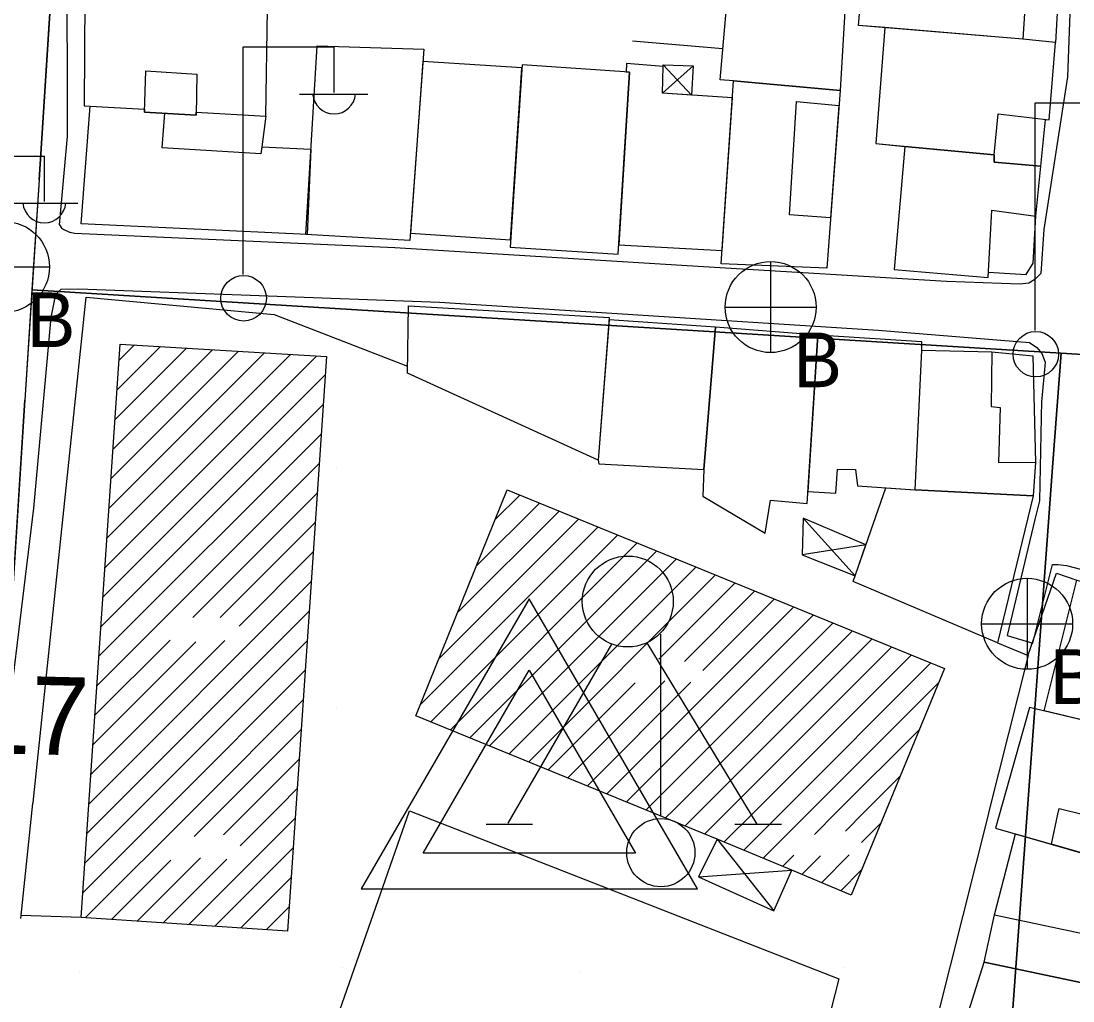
# Model space of a CAD drawing. Extents: x 417997 to 421451, y 4451742 to 4455216.
# Drawn here: x 419832.6 to 419913.6, y 4453026.6 to 4453102 of the extents above; entities that cross this region are included whole.
import ezdxf

# ---------------------------------------------------------------- set-up
doc = ezdxf.new("R2010")
doc.units = 0
for name, color, linetype in [('ADA', 7, 'Continuous'), ('ADAKENARI', 7, 'Continuous'), ('B_Mesken', 7, 'Continuous'), ('B_Okul', 7, 'Continuous'), ('B_Spor_Tesisleri', 7, 'Continuous'), ('B_Sundurma', 7, 'Continuous'), ('B_Tarama', 7, 'Continuous'), ('B_Teras', 7, 'Continuous'), ('Default', 7, 'Continuous'), ('LJ_SEMBOL', 7, 'Continuous'), ('PL_AYA_PARK_DINLENME', 7, 'Continuous'), ('PL_EĞİTİM', 7, 'Continuous'), ('PL_TİCK', 7, 'Continuous'), ('S_Bayrak_Diregi', 7, 'Continuous'), ('S_Elektrik_Diregi', 7, 'Continuous'), ('S_Heykel', 7, 'Continuous'), ('S_Rogar_Kapagi_Buski', 7, 'Continuous'), ('Sinir_Duvar_tek_tarafa_ait', 7, 'Continuous'), ('TR_EĞİTİM', 7, 'Continuous'), ('TR_TİCK', 7, 'Continuous'), ('Y_Yol_Kotu', 7, 'Continuous'), ('Yol_Sose', 7, 'Continuous')]:
    doc.layers.add(name, color=color, linetype=linetype)

# ---------------------------------------------------------------- blocks, each defined once
blk = doc.blocks.new('POINT_DISPLAY')
at = {"layer": 'Default'}
blk.add_line((0, 0), (0, 0), dxfattribs=at)

msp = doc.modelspace()

# ---------------------------------------------------------------- linework, layer by layer
at = {"layer": 'ADA'}
for p, q in [((419951.154, 4453074.072), (419833.483, 4453081.316)), ((419951.154, 4453074.072), (419833.483, 4453081.316)), ((419912.691, 4453076.44), (419912.059, 4453068.004)), ((419912.691, 4453076.44), (419912.059, 4453068.004)), ((419905.437, 4452977.718), (419912.059, 4453068.004)), ((419905.437, 4452977.718), (419912.059, 4453068.004))]:
    msp.add_line(p, q, dxfattribs=at)
at = {"layer": 'ADAKENARI'}
for p, q in [((419834.027, 4453089.798), (419841.779, 4453210.729)), ((419834.027, 4453089.798), (419841.779, 4453210.729)), ((419834.027, 4453089.798), (419832.939, 4453072.833)), ((419834.027, 4453089.798), (419832.939, 4453072.833)), ((419830.093, 4453028.46), (419832.939, 4453072.833)), ((419830.093, 4453028.46), (419832.939, 4453072.833))]:
    msp.add_line(p, q, dxfattribs=at)
at = {"layer": 'B_Mesken'}
for points in [[(419912.76, 4453109.492), (419912.249, 4453100.365), (419909.73, 4453100.607), (419899.124, 4453101.5), (419897.089, 4453101.672), (419897.842, 4453110.551), (419898.362, 4453110.516), (419908.156, 4453109.853), (419910.33, 4453109.706)], [(419887.48, 4453097.401), (419886.457, 4453097.488), (419887.377, 4453108.059), (419896.334, 4453107.579), (419895.672, 4453096.673), (419895.672, 4453096.673), (419895.672, 4453096.673)], [(419846.114, 4453095.004), (419851.487, 4453094.675), (419851.61, 4453102.935), (419837.555, 4453103.855), (419837.512, 4453095.489), (419842.152, 4453095.224), (419842.144, 4453095.006), (419846.109, 4453094.775)], [(419911.125, 4453090.846), (419911.48, 4453094.436), (419911.76, 4453094.404), (419912.249, 4453100.365), (419909.73, 4453100.607), (419899.124, 4453101.5), (419898.436, 4453092.571), (419898.436, 4453092.571), (419900.66, 4453092.36), (419907.525, 4453091.709), (419907.534, 4453091.153)], [(419855.422, 4453100.093), (419863.647, 4453099.837), (419862.575, 4453085.128), (419854.553, 4453085.575)], [(419871.185, 4453098.399), (419863.577, 4453098.886), (419862.615, 4453085.67), (419870.316, 4453085.18)], [(419871.2, 4453098.623), (419870.278, 4453084.602), (419878.603, 4453084.075), (419879.459, 4453098.082)], [(419878.646, 4453084.778), (419886.59, 4453084.354), (419887.39, 4453096.087), (419882.002, 4453096.446), (419882.066, 4453098.508), (419879.252, 4453098.748), (419879.221, 4453098.097), (419879.459, 4453098.082)], [(419886.52, 4453083.315), (419887.48, 4453097.401), (419895.672, 4453096.673), (419894.658, 4453082.983)], [(419851.167, 4453092.337), (419854.947, 4453092.149), (419854.67, 4453085.568), (419837.26, 4453086.406), (419837.956, 4453095.463), (419842.152, 4453095.224), (419842.144, 4453095.006), (419843.745, 4453094.913), (419846.109, 4453094.775), (419846.114, 4453095.004), (419851.487, 4453094.675)], [(419907.088, 4453082.688), (419909.991, 4453082.499), (419910.533, 4453083.385), (419910.741, 4453086.987), (419911.125, 4453090.846), (419907.534, 4453091.153), (419907.525, 4453091.709), (419900.66, 4453092.36), (419899.844, 4453082.875), (419907.063, 4453082.27)], [(419862.386, 4453074.902), (419862.461, 4453080.093), (419877.915, 4453079.194), (419877.052, 4453068.221)], [(419877.052, 4453068.221), (419877.113, 4453067.929), (419885.192, 4453067.495), (419886.101, 4453078.439), (419877.9, 4453079.008)], [(419885.192, 4453067.495), (419885.117, 4453065.441), (419889.914, 4453062.6), (419890.313, 4453065.126), (419893.136, 4453064.869), (419893.964, 4453077.833), (419886.101, 4453078.439)], [(419901.964, 4453076.668), (419901.964, 4453077.308), (419893.964, 4453077.833), (419893.195, 4453065.796), (419895.35, 4453065.681), (419895.482, 4453067.51), (419896.872, 4453067.5), (419897.006, 4453066.233), (419901.454, 4453065.923), (419901.964, 4453076.668)], [(419907.35, 4453076.547), (419910.502, 4453076.242), (419910.71, 4453068.072), (419910.537, 4453065.469), (419901.454, 4453065.923), (419901.964, 4453076.668)], [(419896.677, 4453058.877), (419899.188, 4453066.081), (419901.454, 4453065.923), (419910.537, 4453065.469), (419907.8, 4453054.166)], [(419911.39, 4453048.913), (419913.893, 4453058.99), (419925.145, 4453056.243), (419922.654, 4453046.227)], [(419920.367, 4453036.223), (419922.885, 4453046.172), (419910.25, 4453049.185), (419907.645, 4453039.907)], [(419907.556, 4453033.222), (419909.171, 4453039.472), (419911.956, 4453038.678), (419911.956, 4453038.678), (419919.526, 4453036.468), (419918.593, 4453030.881), (419917.597, 4453027.299), (419906.776, 4453029.582)], [(419917.597, 4453027.299), (419917.979, 4453027.214), (419915.495, 4453017.164), (419903.727, 4453020.002), (419906.776, 4453029.582)]]:
    msp.add_lwpolyline(points, close=True, dxfattribs=at)
at = {"layer": 'B_Okul'}
for points in [[(419856.159, 4453076.181), (419853.154, 4453031.983), (419837.274, 4453033.034), (419840.277, 4453077.148)], [(419870.056, 4453065.931), (419903.709, 4453052.195), (419896.523, 4453034.74), (419891.955, 4453036.655), (419886.224, 4453039.063), (419863.018, 4453048.547)]]:
    msp.add_lwpolyline(points, close=True, dxfattribs=at)
at = {"layer": 'B_Spor_Tesisleri'}
msp.add_lwpolyline([(419855.504, 4453021.12), (419862.527, 4453041.227), (419895.593, 4453028.3), (419890.232, 4453007.29)], close=True, dxfattribs=at)
at = {"layer": 'B_Sundurma'}
for p, q in [((419882.002, 4453096.446), (419884.37, 4453098.554)), ((419882.065, 4453098.643), (419884.246, 4453096.296)), ((419892.847, 4453063.744), (419896.83, 4453059.316)), ((419897.661, 4453061.701), (419892.764, 4453060.939)), ((419886.224, 4453039.063), (419890.587, 4453033.548)), ((419884.781, 4453036.141), (419891.955, 4453036.655))]:
    msp.add_line(p, q, dxfattribs=at)
for points in [[(419882.002, 4453096.446), (419882.066, 4453098.508), (419882.065, 4453098.643), (419884.37, 4453098.554), (419884.246, 4453096.296)], [(419897.661, 4453061.701), (419892.847, 4453063.744), (419892.764, 4453060.939), (419896.83, 4453059.316)], [(419886.224, 4453039.063), (419884.781, 4453036.141), (419890.587, 4453033.548), (419891.955, 4453036.655)]]:
    msp.add_lwpolyline(points, close=True, dxfattribs=at)
at = {"layer": 'B_Tarama'}
for p, q in [((419839.727, 4453069.072), (419847.372, 4453076.717)), ((419839.882, 4453071.348), (419845.372, 4453076.838)), ((419840.037, 4453073.624), (419843.372, 4453076.96)), ((419840.192, 4453075.901), (419841.373, 4453077.082)), ((419839.107, 4453059.967), (419855.37, 4453076.23)), ((419839.262, 4453062.243), (419853.37, 4453076.351)), ((419839.417, 4453064.519), (419851.371, 4453076.473)), ((419839.572, 4453066.796), (419849.371, 4453076.595)), ((419838.952, 4453057.69), (419856.066, 4453074.804)), ((419838.797, 4453055.414), (419855.911, 4453072.528)), ((419838.642, 4453053.138), (419855.756, 4453070.252)), ((419838.487, 4453050.862), (419855.602, 4453067.976)), ((419845.854, 4453056.107), (419855.447, 4453065.7)), ((419869.118, 4453063.616), (419871.034, 4453065.531)), ((419867.676, 4453060.052), (419872.54, 4453064.916)), ((419864.79, 4453052.923), (419875.553, 4453063.687)), ((419866.233, 4453056.487), (419874.047, 4453064.302)), ((419847.979, 4453056.11), (419855.292, 4453063.424)), ((419863.347, 4453049.359), (419877.06, 4453063.072)), ((419864.181, 4453048.072), (419878.566, 4453062.457)), ((419865.687, 4453047.457), (419880.073, 4453061.842)), ((419849.435, 4453055.445), (419855.137, 4453061.148)), ((419867.193, 4453046.841), (419881.579, 4453061.227)), ((419868.699, 4453046.226), (419883.086, 4453060.612)), ((419870.205, 4453045.61), (419884.592, 4453059.997)), ((419837.867, 4453041.756), (419854.982, 4453058.871)), ((419871.711, 4453044.995), (419886.098, 4453059.383)), ((419881.733, 4453052.895), (419887.605, 4453058.768)), ((419883.691, 4453052.733), (419889.111, 4453058.153)), ((419885.102, 4453052.022), (419890.618, 4453057.538)), ((419839.967, 4453041.734), (419854.828, 4453056.595)), ((419877.734, 4453042.533), (419892.124, 4453056.923)), ((419879.24, 4453041.917), (419893.631, 4453056.308)), ((419880.746, 4453041.302), (419895.137, 4453055.693)), ((419882.845, 4453041.28), (419896.644, 4453055.078)), ((419838.022, 4453044.033), (419848.339, 4453054.35)), ((419838.177, 4453046.309), (419846.106, 4453054.237)), ((419838.332, 4453048.585), (419844.121, 4453054.374)), ((419842.066, 4453041.712), (419854.673, 4453054.319)), ((419884.944, 4453041.258), (419898.15, 4453054.464)), ((419887.043, 4453041.235), (419899.657, 4453053.849)), ((419889.142, 4453041.213), (419901.163, 4453053.234)), ((419891.241, 4453041.191), (419902.669, 4453052.619)), ((419844.165, 4453041.69), (419854.518, 4453052.043)), ((419873.217, 4453044.379), (419879.917, 4453051.08)), ((419874.722, 4453043.764), (419882.182, 4453051.224)), ((419876.228, 4453043.148), (419884.203, 4453051.123)), ((419893.34, 4453041.169), (419903.25, 4453051.078)), ((419846.264, 4453041.667), (419854.363, 4453049.767)), ((419848.363, 4453041.645), (419854.209, 4453047.491)), ((419895.439, 4453041.146), (419901.765, 4453047.472)), ((419850.462, 4453041.623), (419854.054, 4453045.215)), ((419897.538, 4453041.124), (419900.28, 4453043.866)), ((419852.561, 4453041.601), (419853.899, 4453042.939)), ((419837.403, 4453034.928), (419844.165, 4453041.69)), ((419837.558, 4453037.204), (419842.066, 4453041.712)), ((419837.608, 4453033.012), (419846.264, 4453041.667)), ((419837.713, 4453039.48), (419839.967, 4453041.734)), ((419845.976, 4453039.258), (419848.363, 4453041.645)), ((419848.22, 4453039.381), (419850.462, 4453041.623)), ((419849.509, 4453038.549), (419852.561, 4453041.601)), ((419882.252, 4453040.687), (419882.845, 4453041.28)), ((419883.758, 4453040.071), (419884.944, 4453041.258)), ((419885.263, 4453039.456), (419887.043, 4453041.235)), ((419886.765, 4453038.836), (419889.142, 4453041.213)), ((419888.259, 4453038.208), (419891.241, 4453041.191)), ((419889.752, 4453037.58), (419893.34, 4453041.169)), ((419893.696, 4453039.403), (419895.439, 4453041.146)), ((419896.093, 4453039.678), (419897.538, 4453041.124)), ((419845.567, 4453032.485), (419853.744, 4453040.663)), ((419897.327, 4453038.792), (419898.796, 4453040.26)), ((419847.556, 4453032.353), (419853.589, 4453038.386)), ((419891.246, 4453036.953), (419892.111, 4453037.818)), ((419892.74, 4453036.326), (419894.179, 4453037.765)), ((419894.235, 4453035.699), (419896.376, 4453037.84)), ((419839.598, 4453032.88), (419844.163, 4453037.446)), ((419841.587, 4453032.748), (419846.457, 4453037.618)), ((419843.577, 4453032.617), (419848.481, 4453037.521)), ((419895.73, 4453035.073), (419897.311, 4453036.654)), ((419849.546, 4453032.222), (419853.435, 4453036.11)), ((419851.536, 4453032.09), (419853.28, 4453033.834))]:
    msp.add_line(p, q, dxfattribs=at)
at = {"layer": 'B_Teras'}
for points in [[(419897.842, 4453110.551), (419910.33, 4453109.706), (419909.73, 4453100.607), (419897.089, 4453101.672)], [(419898.436, 4453092.571), (419907.525, 4453091.709), (419907.846, 4453094.854), (419911.76, 4453094.404), (419912.249, 4453100.365), (419909.73, 4453100.607), (419899.124, 4453101.5)], [(419842.144, 4453095.006), (419842.256, 4453098.171), (419846.18, 4453097.922), (419846.109, 4453094.775)], [(419894.945, 4453086.862), (419891.792, 4453087.094), (419892.33, 4453095.804), (419895.586, 4453095.519)], [(419851.167, 4453092.337), (419851.095, 4453091.785), (419843.497, 4453092.245), (419843.717, 4453094.914), (419846.109, 4453094.775), (419846.114, 4453095.004), (419851.487, 4453094.675)], [(419900.66, 4453092.36), (419899.844, 4453082.875), (419907.063, 4453082.27), (419907.369, 4453087.443), (419910.741, 4453086.987), (419911.125, 4453090.846), (419907.534, 4453091.153), (419907.525, 4453091.709)], [(419901.964, 4453076.668), (419907.35, 4453076.547), (419907.304, 4453072.333), (419907.996, 4453072.271), (419907.881, 4453068.033), (419910.71, 4453068.072), (419910.537, 4453065.469), (419901.454, 4453065.923)], [(419914.413, 4453040.945), (419921.068, 4453039.342), (419920.367, 4453036.223), (419911.956, 4453038.678), (419912.44, 4453040.966), (419912.531, 4453041.398)], [(419906.776, 4453029.582), (419907.556, 4453033.222), (419918.593, 4453030.881), (419917.597, 4453027.299)]]:
    msp.add_lwpolyline(points, close=True, dxfattribs=at)
at = {"layer": 'LJ_SEMBOL'}
for points in [[(419884.7, 4453035.223), (419871.758, 4453057.542), (419858.816, 4453035.223), (419884.7, 4453035.223)], [(419884.7, 4453035.223), (419871.758, 4453057.542), (419858.816, 4453035.223), (419884.7, 4453035.223)], [(419871.758, 4453052.06), (419879.927, 4453037.973), (419863.59, 4453037.973), (419871.758, 4453052.06)], [(419871.758, 4453052.06), (419879.927, 4453037.973), (419863.59, 4453037.973), (419871.758, 4453052.06)]]:
    msp.add_lwpolyline(points, dxfattribs=at)
at = {"layer": 'PL_AYA_PARK_DINLENME'}
msp.add_lwpolyline([(419912.691, 4453076.44), (419912.059, 4453068.004), (419905.437, 4452977.718), (419913.357, 4452974.005), (419938.076, 4452962.417), (419942.978, 4452965.281), (419950.517, 4453065.596), (419951.154, 4453074.072), (419912.691, 4453076.44)], dxfattribs=at)
msp.add_lwpolyline([(419912.691, 4453076.44), (419912.059, 4453068.004), (419905.437, 4452977.718), (419913.357, 4452974.005), (419938.076, 4452962.417), (419942.978, 4452965.281), (419950.517, 4453065.596), (419951.154, 4453074.072), (419912.691, 4453076.44)], dxfattribs=at)
at = {"layer": 'PL_EĞİTİM'}
msp.add_lwpolyline([(419833.483, 4453081.316), (419832.939, 4453072.833), (419830.093, 4453028.46), (419832.318, 4453019.167), (419835.641, 4453013.55), (419842.714, 4453007.124), (419897.31, 4452981.528), (419905.437, 4452977.718), (419912.059, 4453068.004), (419912.691, 4453076.44), (419833.483, 4453081.316)], dxfattribs=at)
msp.add_lwpolyline([(419833.483, 4453081.316), (419832.939, 4453072.833), (419830.093, 4453028.46), (419832.318, 4453019.167), (419835.641, 4453013.55), (419842.714, 4453007.124), (419897.31, 4452981.528), (419905.437, 4452977.718), (419912.059, 4453068.004), (419912.691, 4453076.44), (419833.483, 4453081.316)], dxfattribs=at)
at = {"layer": 'PL_TİCK'}
msp.add_lwpolyline([(419921.488, 4453212.19), (419913.004, 4453212.727), (419842.227, 4453217.214), (419841.779, 4453210.729), (419834.027, 4453089.798), (419833.483, 4453081.316), (419912.691, 4453076.44), (419951.154, 4453074.072), (419955.416, 4453130.78), (419960.857, 4453203.181), (419961.344, 4453209.663), (419929.97, 4453211.652), (419921.488, 4453212.19)], dxfattribs=at)
msp.add_lwpolyline([(419921.488, 4453212.19), (419913.004, 4453212.727), (419842.227, 4453217.214), (419841.779, 4453210.729), (419834.027, 4453089.798), (419833.483, 4453081.316), (419912.691, 4453076.44), (419951.154, 4453074.072), (419955.416, 4453130.78), (419960.857, 4453203.181), (419961.344, 4453209.663), (419929.97, 4453211.652), (419921.488, 4453212.19)], dxfattribs=at)
at = {"layer": 'S_Bayrak_Diregi'}
msp.add_line((419881.878, 4453040.83), (419881.878, 4453054.83), dxfattribs=at)
msp.add_circle((419881.885, 4453038.012), 2.625, dxfattribs=at)
at = {"layer": 'S_Elektrik_Diregi'}
for p, q in [((419849.735, 4453082.508), (419849.735, 4453100.008)), ((419849.735, 4453100.008), (419856.735, 4453100.008)), ((419856.735, 4453096.508), (419856.735, 4453100.008)), ((419854.075, 4453096.368), (419859.325, 4453096.368)), ((419910.704, 4453078.202), (419910.704, 4453095.702)), ((419910.704, 4453095.702), (419917.704, 4453095.702)), ((419827.436, 4453091.619), (419834.436, 4453091.619)), ((419834.436, 4453088.119), (419834.436, 4453091.619)), ((419831.776, 4453087.979), (419837.026, 4453087.979))]:
    msp.add_line(p, q, dxfattribs=at)
for centre in [(419849.771, 4453080.672), (419910.74, 4453076.367)]:
    msp.add_circle(centre, 1.75, dxfattribs=at)
for centre in [(419856.735, 4453096.521), (419834.437, 4453088.132)]:
    msp.add_arc(centre, 1.658, 184.83843, 355.14641, dxfattribs=at)
at = {"layer": 'S_Heykel'}
for p, q in [((419870.123, 4453040.27), (419878.103, 4453054.061)), ((419889.303, 4453040.2), (419880.833, 4453054.166)), ((419868.443, 4453040.2), (419872.013, 4453040.2)), ((419887.588, 4453040.2), (419891.158, 4453040.2))]:
    msp.add_line(p, q, dxfattribs=at)
msp.add_circle((419879.338, 4453057.34), 3.5, dxfattribs=at)
at = {"layer": 'S_Rogar_Kapagi_Buski'}
for p, q in [((419890.333, 4453083.494), (419890.333, 4453076.494)), ((419827.832, 4453083.084), (419834.832, 4453083.084)), ((419886.833, 4453079.994), (419893.833, 4453079.994)), ((419910.073, 4453059.124), (419910.073, 4453052.124)), ((419906.573, 4453055.624), (419913.573, 4453055.624))]:
    msp.add_line(p, q, dxfattribs=at)
for centre in [(419831.332, 4453083.084), (419890.333, 4453079.994), (419910.073, 4453055.624)]:
    msp.add_circle(centre, 3.5, dxfattribs=at)
at = {"layer": 'Sinir_Duvar_tek_tarafa_ait'}
for points in [[(419879.714, 4453100.477), (419886.666, 4453099.888)], [(419833.568, 4453041.862), (419837.654, 4453080.761), (419852.124, 4453079.417), (419862.393, 4453075.435)], [(419910.138, 4453053.16), (419912.327, 4453059.531), (419913.91, 4453058.986)], [(419907.8, 4453054.166), (419910.145, 4453053.187), (419907.104, 4453041.085)], [(419833.562, 4453041.802), (419833.568, 4453041.862)], [(419832.631, 4453032.94), (419833.562, 4453041.802)], [(419907.088, 4453041.023), (419901.196, 4453017.575)], [(419907.104, 4453041.085), (419907.088, 4453041.023)], [(419837.274, 4453033.034), (419832.655, 4453033.169)]]:
    msp.add_lwpolyline(points, dxfattribs=at)
at = {"layer": 'TR_TİCK'}
msp.add_lwpolyline([(419912.691, 4453076.44), (419951.154, 4453074.072), (419955.416, 4453130.78), (419960.857, 4453203.181), (419961.344, 4453209.663), (419929.97, 4453211.652), (419921.488, 4453212.19), (419913.004, 4453212.727), (419842.227, 4453217.214), (419841.779, 4453210.729), (419834.027, 4453089.798), (419833.483, 4453081.316), (419912.691, 4453076.44)], dxfattribs=at)
msp.add_lwpolyline([(419912.691, 4453076.44), (419951.154, 4453074.072), (419955.416, 4453130.78), (419960.857, 4453203.181), (419961.344, 4453209.663), (419929.97, 4453211.652), (419921.488, 4453212.19), (419913.004, 4453212.727), (419842.227, 4453217.214), (419841.779, 4453210.729), (419834.027, 4453089.798), (419833.483, 4453081.316), (419912.691, 4453076.44)], dxfattribs=at)
at = {"layer": 'Yol_Sose'}
for points in [[(419835.609, 4453086.32), (419836.23, 4453093.131), (419836.2, 4453107.58), (419836.146, 4453122.944)], [(419836.146, 4453122.944), (419836.251, 4453123.291), (419836.251, 4453123.291), (419862.822, 4453121.792), (419881.409, 4453121.732), (419901.365, 4453120.542), (419913.263, 4453119.733), (419914, 4453119.481), (419914.15, 4453119.104), (419913.655, 4453111.011), (419913.17, 4453097.706), (419911.355, 4453085.971)], [(419835.609, 4453086.32), (419835.786, 4453086.037), (419836.423, 4453085.729)], [(419911.355, 4453085.971), (419911.133, 4453082.585), (419910.659, 4453082.106), (419910.2, 4453081.843), (419909.501, 4453081.746), (419903.866, 4453081.962), (419885.16, 4453083.079), (419861.407, 4453084.564), (419836.75, 4453085.645), (419836.423, 4453085.729)], [(419834.961, 4453079.203), (419835.309, 4453080.991), (419835.736, 4453081.365), (419837.083, 4453081.393), (419864.84, 4453080.377), (419898.617, 4453078.216), (419910.263, 4453077.257), (419910.815, 4453076.894), (419911.196, 4453076.414), (419911.45, 4453075.758), (419911.173, 4453072.665)], [(419830.866, 4453041.89), (419833.623, 4453064.518), (419834.961, 4453079.203)], [(419911.184, 4453072.785), (419911.036, 4453065.097), (419910.669, 4453063.637), (419908.548, 4453054.73), (419910.503, 4453054.127), (419912.032, 4453060.187)], [(419912.032, 4453060.187), (419912.426, 4453060.175), (419913.107, 4453060.111), (419925.078, 4453056.987), (419925.418, 4453056.7), (419925.536, 4453056.44), (419925.458, 4453055.71), (419923.493, 4453046.718), (419922.283, 4453040.925)]]:
    msp.add_lwpolyline(points, dxfattribs=at)

# ---------------------------------------------------------------- block references
at = {"layer": 'TR_EĞİTİM', "xscale": 0.1, "yscale": 0.10000000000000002}
for p in [(419837.148, 4453067.453), (419837.148, 4453067.453), (419856.901, 4453067.677), (419856.901, 4453067.677), (419875.707, 4453067.453), (419875.707, 4453067.453), (419895.461, 4453067.677), (419895.461, 4453067.677), (419837.148, 4453048.868), (419837.148, 4453048.868), (419856.901, 4453049.092), (419856.901, 4453049.092), (419875.707, 4453048.868), (419875.707, 4453048.868), (419895.461, 4453049.092), (419895.461, 4453049.092), (419837.148, 4453028.868), (419837.148, 4453028.868), (419857.35, 4453029.182), (419857.35, 4453029.182), (419875.707, 4453028.868), (419875.707, 4453028.868), (419895.91, 4453029.182), (419895.91, 4453029.182)]:
    msp.add_blockref('POINT_DISPLAY', p, dxfattribs=at)

# ---------------------------------------------------------------- texts
at = {"layer": 'S_Rogar_Kapagi_Buski'}
for p in [(419833.079, 4453076.92), (419892.079, 4453073.83), (419911.819, 4453049.46)]:
    msp.add_text('B', height=4.2, dxfattribs=at).set_placement(p)
at = {"layer": 'Y_Yol_Kotu'}
msp.add_text('113.17 ', height=6, rotation=358.64456, dxfattribs=at).set_placement((419813.275, 4453046.061))

doc.saveas('drawing.dxf')
